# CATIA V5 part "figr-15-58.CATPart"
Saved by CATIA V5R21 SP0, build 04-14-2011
Part number: Part1
Bounding box of the stored display mesh (mm): x -20 to 20, y -25 to 25, z 0 to 50
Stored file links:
  C:\Users\CADCIM\CATIA_v5r21\c15_cat_v5r21\c15-catia-v5r20-prt\Part1.CATPart
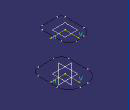
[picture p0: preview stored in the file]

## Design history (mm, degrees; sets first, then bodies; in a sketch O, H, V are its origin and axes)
SheetMetalParameters1: Thickness 2, BendRadius 4, KFactor 0.400515 {= log(min(100,max(20*SheetMetalParameters1.BendRadius,SheetMetalParameters1.Thickness)/SheetMetalParameters1.Thickness))/log(100)/2}, ReliefRadialLength 1, ReliefAxialLength 2, MinimumBendRadius 0
Body1 (main body)
  Plane1: type Offset, RefPlane xy-plane, Offset 50
  Sketch1 on xy-plane, origin (0, 0, 0), H (1, 0, 0), V (0, 1, 0)
    line L1 (20, 10) -> (20, -15)
    line L2 (10, -25) -> (-10, -25)
    line L3 (-20, -15) -> (-20, 10)
    line L4 (-5, 25) -> (5, 25)
    arc A1 centre (5, 10) radius 15 from (20, 10) to (5, 25) ccw
    arc A2 centre (-5, 10) radius 15 from (-20, 10) to (-5, 25) cw
    arc A3 centre (10, -15) radius 10 from (20, -15) to (10, -25) cw
    arc A4 centre (-10, -15) radius 10 from (-10, -25) to (-20, -15) cw
    radius A1 = 15
    radius A2 = 15
    radius A3 = 10
    radius A4 = 10
    distance L4 L2 = 50
    distance L3 L1 = 40
    vertical: L1 V, L3 V
    horizontal: L2 H, L4 H
    equidistance: L1 L3 O, L2 L4 O
    tangency: A1 L1, A1 L4, A2 L3, A2 L4, A3 L1, A3 L2, A4 L2, A4 L3
  Sketch2 on Plane1, origin (0, 0, 50), H (1, 0, 0), V (0, 1, 0)
    line L1 (15, 10) -> (15, -15)
    line L2 (10, -20) -> (-10, -20)
    line L3 (-15, -15) -> (-15, 10)
    line L4 (-5, 20) -> (5, 20)
    arc A1 centre (5, 10) radius 10 from (15, 10) to (5, 20) ccw
    arc A2 centre (10, -15) radius 5 from (15, -15) to (10, -20) cw
    arc A3 centre (-10, -15) radius 5 from (-10, -20) to (-15, -15) cw
    arc A4 centre (-5, 10) radius 10 from (-15, 10) to (-5, 20) cw
    radius A1 = 10
    radius A2 = 5
    radius A3 = 5
    radius A4 = 10
    distance L4 L2 = 40
    distance L1 L3 = 30
    vertical: L1 V, L3 V
    horizontal: L2 H, L4 H
    equidistance: L1 L3 O, L2 L4 O
    tangency: A1 L1, A1 L4, A2 L1, A2 L2, A3 L2, A3 L3, A4 L3, A4 L4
